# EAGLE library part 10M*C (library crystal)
Monolithic Crystal Filters Source: www.vanlong.com
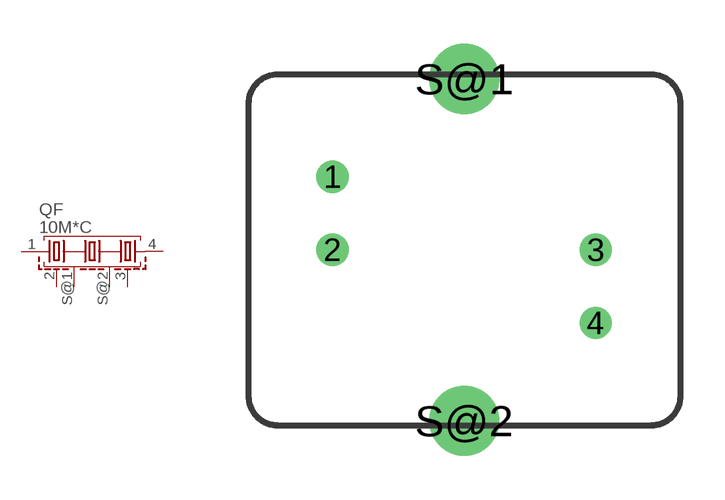
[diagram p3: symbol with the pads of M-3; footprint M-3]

Designator prefix QF

## 10M7C (OC_FARNELL: unknown; OC_NEWARK: unknown), 10M15C (OC_FARNELL: unknown; OC_NEWARK: unknown), 10M20C (OC_FARNELL: unknown; OC_NEWARK: unknown), 10M25C (OC_FARNELL: unknown; OC_NEWARK: unknown), 10M30C (OC_FARNELL: unknown; OC_NEWARK: unknown)  [M-3]
1  1  pas
2  2  pas
3  3  pas
4  4  pas
S@1  S  pas
S@2  S  pas

## Footprint M-3 (pad centres in mm)
Monolithic Crystal Filters Source: www.vanlong.com
drill 0.6 pad 1.016 round: 1 -4.5,2.5; 2 -4.5,0; 3 4.5,0; 4 4.5,-2.5
drill 1.6 pad 1.93 round: S@1 0,5.85; S@2 0,-5.85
